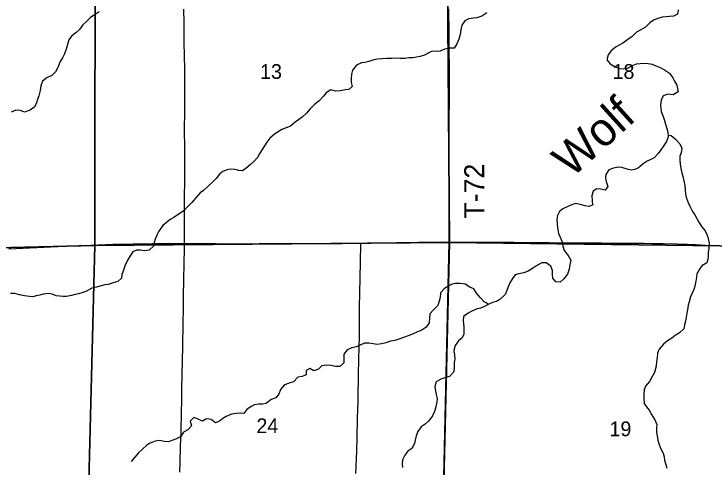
# Model space of a CAD drawing. Extents: x 0 to 34, y 0 to 22.
# Drawn here: x 3.198 to 4.194, y 18.94 to 19.585 of the extents above; entities that cross this region are included whole.
import ezdxf

# ---------------------------------------------------------------- set-up
doc = ezdxf.new("R2010")
doc.units = 0
for name, color, linetype in [('GM_X_Corporation', 7, 'Continuous'), ('GM_X_County_Road', 7, 'Continuous'), ('GM_X_Minor_River', 7, 'Continuous'), ('GM_X_Minor_River_Text', 7, 'Continuous'), ('GM_X_Section_Text', 7, 'Continuous'), ('GM_X_Township_Road', 7, 'Continuous'), ('GM_X_Township_Road_Text', 7, 'Continuous')]:
    doc.layers.add(name, color=color, linetype=linetype)

msp = doc.modelspace()

# ---------------------------------------------------------------- linework, layer by layer
at = {"layer": 'GM_X_Corporation'}
for points in [[(3.31302, 19.75711), (3.31283, 19.25536), (2.81384, 19.2434), (2.81044, 19.74782)], [(3.81367, 19.76242), (3.81726, 19.25969), (3.31283, 19.25536), (3.31302, 19.75711)], [(4.31408, 19.76015), (4.31726, 19.25364), (3.81726, 19.25969), (3.81367, 19.76242)], [(3.31283, 19.25536), (3.81726, 19.25969), (3.80532, 18.75879), (3.29992, 18.75163)], [(3.81726, 19.25969), (4.31726, 19.25364), (4.30478, 18.73265), (3.80532, 18.75879)], [(2.81384, 19.2434), (3.31283, 19.25536), (3.29992, 18.75163), (2.80209, 18.74156)]]:
    msp.add_lwpolyline(points, close=True, dxfattribs=at)
msp.add_lwpolyline([(3.80563, 18.75936), (3.81669, 19.26056), (3.81668, 19.26476), (3.81667, 19.27067), (3.81666, 19.28838), (3.81679, 19.32226), (3.81685, 19.33221), (3.81674, 19.3493), (3.81689, 19.36919), (3.81687, 19.39064), (3.81684, 19.404), (3.81687, 19.44006), (3.81694, 19.45715), (3.81696, 19.47145), (3.81707, 19.4873), (3.81701, 19.50159), (3.81694, 19.51309), (3.81685, 19.52801), (3.8168, 19.53733), (3.8166, 19.5566), (3.81638, 19.59203)], dxfattribs=at)
msp.add_lwpolyline([(3.80563, 18.75936), (3.81669, 19.26056), (3.81668, 19.26476), (3.81667, 19.27067), (3.81666, 19.28838), (3.81679, 19.32226), (3.81685, 19.33221), (3.81674, 19.3493), (3.81689, 19.36919), (3.81687, 19.39064), (3.81684, 19.404), (3.81687, 19.44006), (3.81694, 19.45715), (3.81696, 19.47145), (3.81707, 19.4873), (3.81701, 19.50159), (3.81694, 19.51309), (3.81685, 19.52801), (3.8168, 19.53733), (3.8166, 19.5566), (3.81638, 19.59203)], dxfattribs=at)
at = {"layer": 'GM_X_County_Road'}
for points in [[(3.6911, 19.25886), (3.7005, 19.25904), (3.7235, 19.25917), (3.74245, 19.2596), (3.77317, 19.26), (3.78354, 19.26008), (3.79801, 19.26019), (3.80888, 19.26029), (3.8168, 19.26028)], [(3.8168, 19.26028), (3.82379, 19.26027), (3.85049, 19.26037), (3.86291, 19.26003), (3.87534, 19.25984), (3.89336, 19.25992), (3.90918, 19.25986), (3.92502, 19.2597), (3.94428, 19.2594), (3.95887, 19.25935), (3.97938, 19.25918), (3.99584, 19.25925), (4.02348, 19.2591), (4.0334, 19.25897), (4.04426, 19.25875), (4.05514, 19.25872), (4.06632, 19.25863), (4.07968, 19.25862), (4.09335, 19.25859), (4.10515, 19.25836), (4.12069, 19.25816), (4.14087, 19.2576), (4.15515, 19.25713), (4.16723, 19.25654), (4.18861, 19.2554), (4.19606, 19.25505)], [(3.19028, 19.25069), (3.29017, 19.25525), (3.30693, 19.2559), (3.33861, 19.25699), (3.36719, 19.25775), (3.39452, 19.25823), (3.41679, 19.25818), (3.43172, 19.25798), (3.44027, 19.25801)], [(3.44027, 19.25801), (3.45157, 19.25804), (3.48543, 19.25797), (3.51244, 19.25791), (3.54655, 19.25799), (3.5968, 19.25797), (3.62845, 19.25797), (3.66446, 19.25838), (3.6911, 19.25886)]]:
    msp.add_lwpolyline(points, dxfattribs=at)
at = {"layer": 'GM_X_Minor_River'}
for points in [[(4.14264, 19.59043), (4.14184, 19.58436), (4.13576, 19.58154), (4.13046, 19.58101), (4.12553, 19.58047), (4.12003, 19.57993), (4.11529, 19.57863), (4.10864, 19.5762), (4.10237, 19.57206), (4.09608, 19.56583), (4.08961, 19.56189), (4.08334, 19.55889), (4.07724, 19.55266), (4.07077, 19.54814), (4.06392, 19.54305), (4.05841, 19.54024), (4.05328, 19.53761), (4.04662, 19.53177), (4.04298, 19.52647), (4.04086, 19.51927), (4.04594, 19.51374), (4.05273, 19.50952), (4.05972, 19.5072)], [(3.31887, 19.58752), (3.31183, 19.58282), (3.30669, 19.57943), (3.30174, 19.57509), (3.29583, 19.56943), (3.29106, 19.56282), (3.28553, 19.55791), (3.27944, 19.55301), (3.27581, 19.54791)], [(3.87061, 19.58635), (3.86339, 19.58164), (3.85636, 19.57941), (3.85162, 19.57868), (3.84499, 19.57758), (3.8391, 19.57477), (3.83489, 19.56853), (3.83334, 19.56208), (3.83254, 19.55525), (3.83041, 19.54881), (3.82753, 19.54218), (3.8237, 19.53594), (3.81707, 19.53598), (3.81006, 19.5345), (3.80379, 19.53169), (3.79886, 19.53153), (3.7928, 19.53176), (3.78786, 19.52951), (3.78178, 19.52594), (3.77571, 19.52427), (3.77021, 19.52335), (3.76547, 19.52243), (3.75941, 19.52208), (3.7541, 19.52155), (3.74709, 19.52121), (3.74027, 19.52163), (3.73516, 19.52147), (3.72834, 19.52132), (3.72114, 19.52098), (3.71545, 19.52045), (3.70957, 19.51934), (3.70236, 19.51692), (3.69686, 19.51581), (3.69193, 19.51508), (3.68509, 19.51189), (3.67937, 19.50471), (3.678, 19.49884), (3.67758, 19.4922), (3.67736, 19.48707), (3.67865, 19.48137), (3.67389, 19.47703), (3.66915, 19.47668), (3.66195, 19.47539), (3.65512, 19.47505), (3.64851, 19.47661), (3.64166, 19.47247), (3.63822, 19.46756), (3.63174, 19.46114), (3.62489, 19.45549), (3.61917, 19.44983), (3.61383, 19.44359), (3.60754, 19.43775), (3.6024, 19.43417), (3.59765, 19.43059)], [(3.27581, 19.54791), (3.27369, 19.54147), (3.27194, 19.53464), (3.26963, 19.52782), (3.26675, 19.52252), (3.26292, 19.5159), (3.26003, 19.50832), (3.25678, 19.50246), (3.25106, 19.49661), (3.24498, 19.49417), (3.23832, 19.4889), (3.23582, 19.48227), (3.23483, 19.47563), (3.23308, 19.46842), (3.23096, 19.46312), (3.22961, 19.45819), (3.22673, 19.45213), (3.22045, 19.44762), (3.21305, 19.44519), (3.20643, 19.44732), (3.20019, 19.44792), (3.19373, 19.44492)], [(4.05972, 19.5072), (4.0654, 19.50679), (4.07052, 19.50771), (4.0785, 19.51164), (4.08344, 19.51389), (4.08856, 19.51443), (4.09481, 19.51477), (4.09973, 19.51437), (4.1056, 19.51319), (4.1107, 19.51088), (4.11618, 19.50895), (4.12335, 19.5053), (4.13014, 19.50033), (4.13484, 19.49403), (4.13746, 19.48889), (4.14064, 19.48318), (4.14175, 19.47843), (4.14248, 19.47368), (4.13525, 19.46954), (4.12806, 19.47072), (4.12123, 19.4683), (4.11816, 19.46224), (4.11755, 19.45522), (4.11809, 19.45047), (4.11862, 19.44572), (4.12105, 19.43906), (4.1229, 19.43298), (4.12439, 19.42803), (4.12662, 19.42157), (4.12791, 19.41662), (4.12844, 19.40997), (4.12594, 19.40334), (4.12116, 19.39635), (4.11772, 19.39143), (4.11409, 19.38633), (4.10855, 19.3801), (4.10381, 19.37785), (4.09849, 19.37541), (4.09259, 19.37146), (4.0863, 19.36599), (4.08098, 19.36337), (4.07624, 19.36245), (4.07, 19.36381), (4.06263, 19.36613), (4.05752, 19.36692), (4.05069, 19.36545), (4.04405, 19.36283), (4.03984, 19.3564), (4.03924, 19.35109), (4.04034, 19.34633), (4.04238, 19.33911), (4.03856, 19.33401), (4.03213, 19.33556), (4.02683, 19.33578), (4.0217, 19.33259), (4.01957, 19.32577), (4.02029, 19.31931), (4.02063, 19.31285), (4.01531, 19.31079), (4.01039, 19.31177), (4.0032, 19.31371), (3.99677, 19.31508), (3.99203, 19.31359), (3.98538, 19.31078), (3.97835, 19.3076), (3.97359, 19.30345), (3.9711, 19.29796), (3.97011, 19.29189), (3.97046, 19.28638), (3.97079, 19.27993), (3.97245, 19.27251), (3.97488, 19.26737), (3.97768, 19.26071), (3.9784, 19.25425), (3.98063, 19.24817), (3.98608, 19.24092), (3.98983, 19.23444), (3.98846, 19.228), (3.98729, 19.22174), (3.98516, 19.21454), (3.98, 19.20773), (3.97448, 19.20321), (3.96842, 19.20363), (3.9641, 19.20878), (3.96375, 19.21353), (3.96379, 19.2196), (3.96136, 19.22607), (3.95495, 19.23085), (3.94851, 19.23051), (3.94262, 19.22751), (3.93691, 19.22356), (3.92931, 19.21886), (3.92323, 19.21662), (3.91584, 19.21495), (3.91071, 19.21346), (3.90689, 19.20817), (3.90287, 19.20212), (3.90057, 19.19663), (3.89864, 19.19151), (3.89633, 19.18545), (3.88909, 19.17847)], [(3.59765, 19.43059), (3.59098, 19.42512), (3.58472, 19.42288), (3.57864, 19.42026), (3.57256, 19.4165), (3.5678, 19.4133), (3.56152, 19.40821), (3.55731, 19.40216), (3.55387, 19.39706), (3.55062, 19.39176), (3.54756, 19.38665), (3.54392, 19.3806), (3.53934, 19.37531), (3.53382, 19.37003), (3.52753, 19.36475), (3.52259, 19.36174), (3.51767, 19.36196), (3.51237, 19.36332), (3.50594, 19.36412), (3.501, 19.36301), (3.49474, 19.36077), (3.48998, 19.357), (3.4854, 19.35057), (3.48063, 19.34566), (3.47339, 19.33925), (3.46711, 19.33378), (3.46235, 19.3302), (3.45605, 19.32284), (3.4509, 19.31641), (3.4448, 19.31075), (3.43927, 19.30471), (3.43129, 19.29963), (3.42501, 19.2953), (3.42006, 19.29211), (3.41455, 19.28796), (3.40959, 19.28362), (3.40386, 19.27587), (3.40118, 19.27077), (3.39849, 19.26414), (3.39732, 19.2594), (3.39653, 19.25466), (3.39006, 19.24881), (3.38342, 19.2479), (3.37699, 19.24851), (3.37206, 19.24873), (3.36675, 19.24629), (3.36292, 19.24043), (3.3589, 19.23343), (3.35602, 19.22718), (3.35332, 19.22036), (3.3512, 19.21411), (3.3506, 19.20861), (3.34565, 19.20408), (3.339, 19.20203), (3.33179, 19.19979), (3.32706, 19.19925), (3.32004, 19.1974), (3.31491, 19.1961), (3.30865, 19.19443), (3.29991, 19.18973), (3.29441, 19.18786), (3.28928, 19.18657), (3.28454, 19.18545), (3.27961, 19.18434), (3.27259, 19.18287), (3.26786, 19.18252), (3.26275, 19.1833), (3.25782, 19.18371), (3.25197, 19.18584), (3.24667, 19.1872), (3.23928, 19.18629), (3.23434, 19.18442), (3.22941, 19.1835), (3.22467, 19.18239), (3.21956, 19.18261), (3.21256, 19.1836), (3.20575, 19.18497), (3.19875, 19.1871), (3.19288, 19.18694)], [(4.12821, 19.41289), (4.13243, 19.41185), (4.13846, 19.40688), (4.14486, 19.40001), (4.14766, 19.39354), (4.14667, 19.38728), (4.14512, 19.38216), (4.14471, 19.37666), (4.14525, 19.37134), (4.14634, 19.36488), (4.14801, 19.3586), (4.1493, 19.35328), (4.15078, 19.34739), (4.15187, 19.34074), (4.1524, 19.33371), (4.15312, 19.32877), (4.15404, 19.32402), (4.15609, 19.31755), (4.15908, 19.31127), (4.16301, 19.30384), (4.1662, 19.29889), (4.16901, 19.29393), (4.17182, 19.2886), (4.17556, 19.28232), (4.18102, 19.2764), (4.18401, 19.27012), (4.18512, 19.26517), (4.18659, 19.25871), (4.18598, 19.25169), (4.18537, 19.24524), (4.18515, 19.2405), (4.18455, 19.23537), (4.18319, 19.23064), (4.17635, 19.2265), (4.17272, 19.22159), (4.16927, 19.21477), (4.16867, 19.21003), (4.16769, 19.20472), (4.16651, 19.19752), (4.16496, 19.19259), (4.16266, 19.18767), (4.16035, 19.18218), (4.15822, 19.17536), (4.15687, 19.17043), (4.15588, 19.16398), (4.15471, 19.15924), (4.15411, 19.15336), (4.15294, 19.14767), (4.15177, 19.14255), (4.15078, 19.13668), (4.14469, 19.13121), (4.13841, 19.12707), (4.13347, 19.12368), (4.12738, 19.11973), (4.12148, 19.11483), (4.11537, 19.10765), (4.11306, 19.10197), (4.11264, 19.09533), (4.11185, 19.0904), (4.11143, 19.08376), (4.1091, 19.07485), (4.10489, 19.06804), (4.10201, 19.06179), (4.09591, 19.05538), (4.09398, 19.04988), (4.09375, 19.04324), (4.09372, 19.03774), (4.09443, 19.03071), (4.09743, 19.02594), (4.10119, 19.02118), (4.10475, 19.0147), (4.10943, 19.00708), (4.11204, 19.00042), (4.11182, 18.99492), (4.11198, 18.98998), (4.11251, 18.98447), (4.11342, 18.97859), (4.1151, 18.97364), (4.11752, 18.96717), (4.12145, 18.95974), (4.12274, 18.95461), (4.12328, 18.94986), (4.12514, 18.94378), (4.12643, 18.93865)], [(3.87225, 19.17139), (3.87144, 19.17288), (3.86653, 19.17538), (3.86126, 19.18092), (3.85638, 19.18721), (3.85206, 19.1935), (3.8462, 19.19581), (3.8396, 19.20022), (3.8326, 19.2014), (3.82597, 19.20144), (3.82123, 19.20014), (3.81629, 19.1977), (3.81001, 19.19394), (3.80467, 19.18789), (3.80387, 19.18145), (3.8027, 19.17633), (3.80058, 19.17008), (3.79391, 19.16347), (3.78914, 19.15799), (3.78891, 19.15173), (3.7883, 19.14528), (3.78429, 19.13904), (3.77801, 19.13471), (3.77156, 19.13247), (3.76548, 19.12985), (3.75978, 19.12742), (3.75181, 19.12443), (3.74497, 19.122), (3.73966, 19.12032), (3.73321, 19.11941), (3.72657, 19.11698), (3.72069, 19.11531), (3.71443, 19.11459), (3.70856, 19.11519), (3.70251, 19.11656), (3.69645, 19.11621), (3.69094, 19.11378), (3.68486, 19.11097), (3.67822, 19.10967), (3.67177, 19.10687), (3.6668, 19.10063), (3.66672, 19.08829), (3.6612, 19.08339), (3.65495, 19.08305), (3.64852, 19.08441), (3.64227, 19.08483), (3.63564, 19.08411), (3.63068, 19.0792), (3.62423, 19.07696), (3.61837, 19.08023), (3.61324, 19.0776), (3.6132, 19.07114), (3.6077, 19.0689), (3.60144, 19.0678), (3.59515, 19.06119), (3.58908, 19.05952), (3.58262, 19.0569), (3.5769, 19.05029), (3.57439, 19.04366), (3.57019, 19.03837), (3.56355, 19.03632), (3.5567, 19.03048), (3.55101, 19.02937), (3.54608, 19.02959), (3.53983, 19.02849), (3.53508, 19.02643), (3.52918, 19.02191), (3.5246, 19.01624), (3.5193, 19.01684), (3.5138, 19.01611), (3.50717, 19.01539), (3.49957, 19.01221), (3.49462, 19.00901), (3.48987, 19.00543), (3.48455, 19.003), (3.47814, 19.00778), (3.4717, 19.00858), (3.466, 19.00538), (3.45958, 19.00846), (3.45372, 19.01058), (3.4482, 19.0053), (3.45043, 18.99883), (3.44509, 18.99298), (3.43901, 18.9896), (3.43518, 18.98355), (3.42872, 18.98036), (3.42227, 18.97793), (3.41752, 18.97606), (3.41127, 18.97647), (3.40503, 18.97803), (3.39839, 18.97674), (3.39156, 18.97431), (3.3868, 18.97111), (3.38071, 18.96564), (3.3748, 18.96017), (3.36965, 18.95432), (3.3645, 18.94808)], [(3.88909, 19.17847), (3.88396, 19.17566), (3.87845, 19.17398), (3.87219, 19.17136), (3.86687, 19.16873), (3.86136, 19.1663), (3.85643, 19.165), (3.84883, 19.16201), (3.8437, 19.15919), (3.83723, 19.15448), (3.83662, 19.14822), (3.83789, 19.13967), (3.83786, 19.13398), (3.83764, 19.12923), (3.83514, 19.12393), (3.83019, 19.1196), (3.82523, 19.11317), (3.82367, 19.10597), (3.82438, 19.09913), (3.82473, 19.09419), (3.82412, 19.08831), (3.8237, 19.08186), (3.82329, 19.0756), (3.81737, 19.06899), (3.81073, 19.06694), (3.80504, 19.06527), (3.7982, 19.06151), (3.79626, 19.0545), (3.79735, 19.04804), (3.79827, 19.04329), (3.79975, 19.03758), (3.79934, 19.03284), (3.79778, 19.02582), (3.79585, 19.01938), (3.79296, 19.01276), (3.788, 19.00595), (3.78266, 19.00124), (3.77696, 18.99729), (3.77199, 18.99086), (3.76987, 18.98442), (3.7685, 18.97835), (3.76734, 18.97361), (3.76351, 18.96661), (3.75818, 18.96266), (3.75378, 18.9568), (3.75033, 18.95037), (3.74992, 18.9443), (3.75064, 18.93955)]]:
    msp.add_lwpolyline(points, dxfattribs=at)
at = {"layer": 'GM_X_Township_Road'}
for points in [[(3.44027, 19.25801), (3.4403, 19.26748), (3.44052, 19.28023), (3.44041, 19.29017), (3.44031, 19.30198), (3.44046, 19.3169), (3.44051, 19.33119), (3.44053, 19.34082), (3.44057, 19.36165), (3.4406, 19.37874), (3.44058, 19.39863), (3.44048, 19.41479), (3.44052, 19.42722), (3.44057, 19.4387), (3.44058, 19.45609), (3.44059, 19.47194), (3.44066, 19.48872), (3.4406, 19.50675), (3.44036, 19.52477), (3.44003, 19.54435), (3.43988, 19.55398), (3.43962, 19.572), (3.4392, 19.59158)], [(3.8168, 19.26028), (3.81679, 19.26449), (3.81678, 19.27039), (3.81677, 19.28811), (3.8169, 19.32198), (3.81697, 19.33193), (3.81685, 19.34902), (3.817, 19.36891), (3.81698, 19.39036), (3.81695, 19.40373), (3.81698, 19.43978), (3.81705, 19.45687), (3.81708, 19.47117), (3.81718, 19.48702), (3.81712, 19.50132), (3.81705, 19.51282), (3.81696, 19.52773), (3.81691, 19.53706), (3.81671, 19.55632), (3.81649, 19.59176)], [(3.6911, 19.25886), (3.7005, 19.25904), (3.7235, 19.25917), (3.74245, 19.2596), (3.77317, 19.26), (3.78354, 19.26008), (3.79801, 19.26019), (3.80888, 19.26029), (3.8168, 19.26028)], [(3.8168, 19.26028), (3.82379, 19.26027), (3.85049, 19.26037), (3.86291, 19.26003), (3.87534, 19.25984), (3.89336, 19.25992), (3.90918, 19.25986), (3.92502, 19.2597), (3.94428, 19.2594), (3.95887, 19.25935), (3.97938, 19.25918), (3.99584, 19.25925), (4.02348, 19.2591), (4.0334, 19.25897), (4.04426, 19.25875), (4.05514, 19.25872), (4.06632, 19.25863), (4.07968, 19.25862), (4.09335, 19.25859), (4.10515, 19.25836), (4.12069, 19.25816), (4.14087, 19.2576), (4.15515, 19.25713), (4.16723, 19.25654), (4.18861, 19.2554), (4.19606, 19.25505)], [(3.19028, 19.25069), (3.29017, 19.25525), (3.30693, 19.2559), (3.33861, 19.25699), (3.36719, 19.25775), (3.39452, 19.25823), (3.41679, 19.25818), (3.43172, 19.25798), (3.44027, 19.25801)], [(3.43341, 18.93298), (3.43389, 18.94693), (3.43458, 18.96928), (3.43531, 18.99038), (3.43619, 19.01861), (3.43652, 19.03475), (3.43669, 19.05431), (3.43681, 19.06954), (3.43739, 19.09315), (3.43773, 19.10993), (3.43838, 19.14691), (3.43865, 19.164), (3.43893, 19.18265), (3.43935, 19.20689), (3.43976, 19.22989), (3.44024, 19.25039), (3.44027, 19.25801)], [(3.44027, 19.25801), (3.45157, 19.25804), (3.48543, 19.25797), (3.51244, 19.25791), (3.54655, 19.25799), (3.5968, 19.25797), (3.62845, 19.25797), (3.66446, 19.25838), (3.6911, 19.25886)], [(3.68416, 18.93071), (3.68485, 18.95183), (3.68522, 18.96363), (3.68575, 18.98072), (3.68661, 19.00961), (3.68721, 19.03447), (3.68778, 19.07487), (3.68816, 19.0901), (3.68836, 19.09755), (3.68869, 19.10686), (3.68887, 19.11306), (3.68904, 19.12362), (3.68925, 19.15469), (3.68942, 19.16525), (3.68983, 19.1898), (3.69011, 19.20752), (3.69054, 19.23331), (3.69105, 19.25632), (3.6911, 19.25886)]]:
    msp.add_lwpolyline(points, dxfattribs=at)

# ---------------------------------------------------------------- texts
at = {"layer": 'GM_X_Minor_River_Text'}
msp.add_text('Wolf', height=0.047372, rotation=42.103, dxfattribs=at).set_placement((3.99084, 19.35024))
at = {"layer": 'GM_X_Section_Text'}
for s, p in [('13', (3.54778, 19.49237)), ('18', (4.04923, 19.49237)), ('24', (3.54257, 18.98836)), ('19', (4.04486, 18.98404))]:
    msp.add_text(s, height=0.020928, rotation=0.00001, dxfattribs=at).set_placement(p)
at = {"layer": 'GM_X_Township_Road_Text'}
msp.add_text('T-72', height=0.028409, rotation=90, dxfattribs=at).set_placement((3.86667, 19.29359))

doc.saveas('drawing.dxf')
